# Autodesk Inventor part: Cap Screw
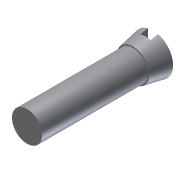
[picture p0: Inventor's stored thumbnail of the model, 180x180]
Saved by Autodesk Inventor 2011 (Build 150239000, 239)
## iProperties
Shininess: 77.0
Length Units: 11269
Angle Units: 11279
Time Units: 11290
Mass Units: 11283
Length Display Precision: 3
Angle Display Precision: 2
Created: 2002-02
Part Number: Cap Screw
Document SubType Name: Modeling
Designer: ***
Density: 1 g/cm^3
Mass: 0.736583 g
Surface Area: 5.87035 cm^2
Volume: 0.736583 cm^3
Density: 0.0
Volumn: 0.0
Area: 0.0
PropertySet Name: Model Information
Control State: 0
Master: False
Checked Out: False
Author: ***
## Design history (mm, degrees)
sketch "Sketch1"
  geometry: L1 (0, 27.83)-(4, 27.83); L2 (4, 27.83)-(3.25, 23.83); L3 (3.25, 23.83)-(0, 23.83); L4 (0, 23.83)-(0, 27.83)
  constraints: 8 end point, 1 horizontal, 1 parallel, 1 perpendicular, 1 point on line
  dimensions: "d2" = 4 distance from line of L1 L2.end; "d5" = 8 diameter of L1.end L4; "d6" = 6.5 diameter of L3.start L4; "d14" = 4 distance of L3.end L1.start
revolve "Revolution1" sketch "Sketch1" stored, may be unused: angle "d7" = 90 deg
sketch "Sketch2"
  geometry: C1 r 3 at (0, 0)
  constraints: 1 centre point
  dimensions: "d8" = 6 diameter of C1
extrude "Extrusion1" join sketch "Sketch2" distance "d9" = 21; taper "d10" = 0 deg
sketch "Sketch3"
  geometry: L1 (-1, 28.967)-(1, 28.967); L2 (1, 28.967)-(1, 26.33); L3 (1, 26.33)-(-1, 26.33); L4 (-1, 26.33)-(-1, 28.967); L5 (-4, 27.83)-(4, 27.83) reference
  constraints: 8 end point, 2 parallel, 1 horizontal, 1 perpendicular
  dimensions: "d11" = 2 distance of L1.start L1.end; "d15" = 1.5 distance between parallel lines of L5 L3
extrude "Extrusion2" cut sketch "Sketch3" stored distance "d12" = 24; taper "d13" = 0 deg
body "Solid1"
